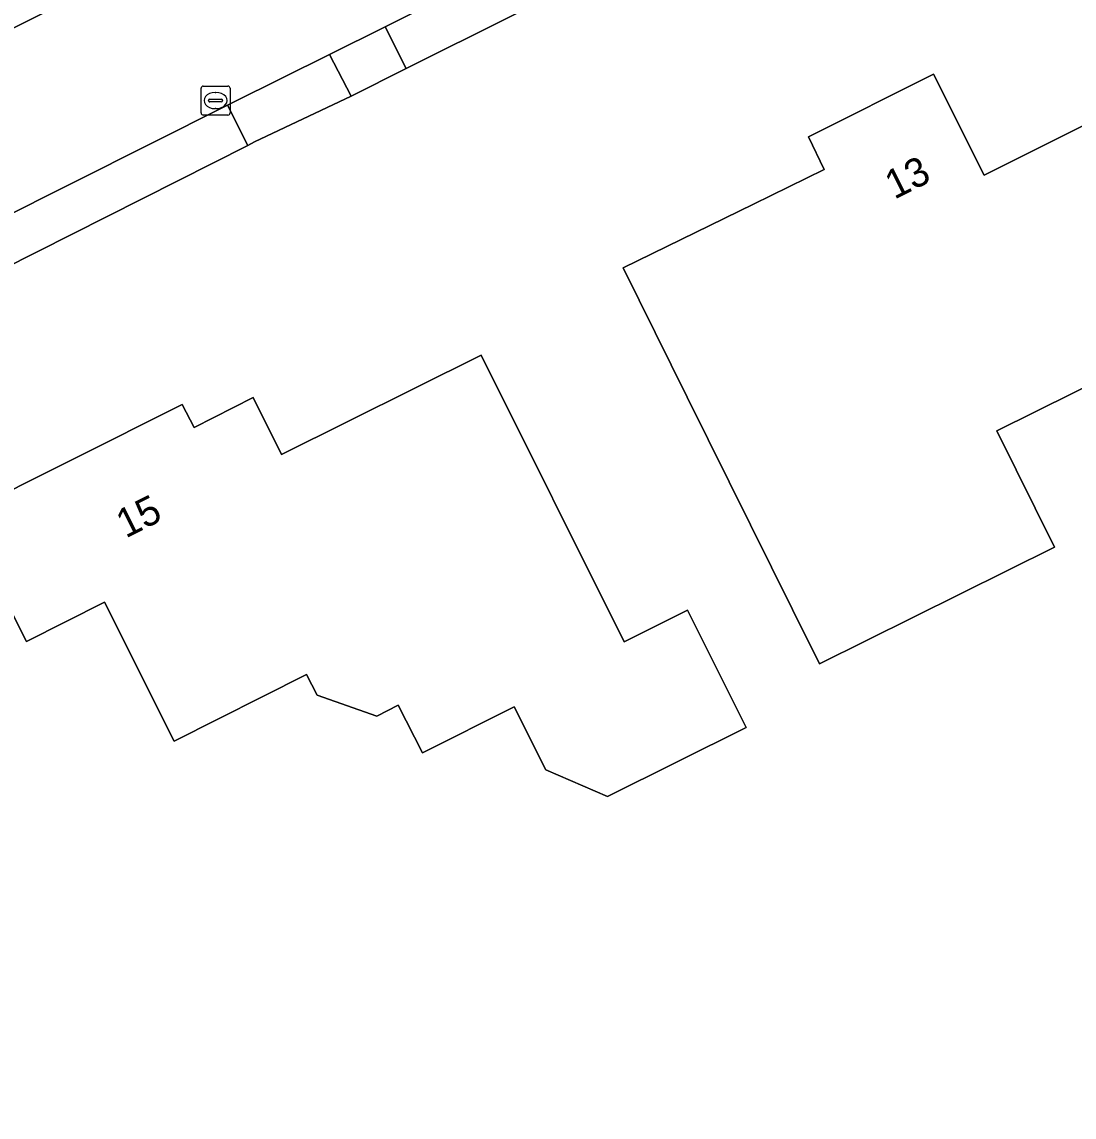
# Model space of a CAD drawing. Extents: x 157320 to 158835, y 386650 to 388491.
# Drawn here: x 158396.47 to 158432.92, y 387023.73 to 387061.67 of the extents above; entities that cross this region are included whole.
import ezdxf

# ---------------------------------------------------------------- set-up
doc = ezdxf.new("R2010")
doc.units = 0
for name, color, linetype in [('IMGEO_Berm_groen', 7, 'Continuous'), ('IMGEO_Erf', 7, 'Continuous'), ('IMGEO_Groenvoorziening', 7, 'Continuous'), ('IMGEO_Kolk', 7, 'Continuous'), ('IMGEO_Pand', 7, 'Continuous'), ('IMGEO_Pand_nummerreeks', 7, 'Continuous'), ('IMGEO_Rijbaan_lokaal_gesloten', 7, 'Continuous'), ('IMGEO_Voetpad_halfverhard', 7, 'Continuous'), ('IMGEO_Voetpad_open', 7, 'Continuous')]:
    doc.layers.add(name, color=color, linetype=linetype)

msp = doc.modelspace()

# ---------------------------------------------------------------- linework, layer by layer
at = {"layer": 'IMGEO_Berm_groen'}
msp.add_lwpolyline([(158415.179, 387070.996), (158413.936, 387073.552), (158390.827, 387061.949), (158390.738, 387061.906), (158392.005, 387059.378)], close=True, dxfattribs=at)
at = {"layer": 'IMGEO_Erf'}
msp.add_lwpolyline([(158424.326, 387067.316), (158409.775, 387060.049), (158407.876, 387059.101), (158404.527, 387057.508), (158404.288, 387057.387), (158390.893, 387050.635), (158390.572, 387050.456), (158388.447, 387049.268), (158387.528, 387048.741), (158381.13, 387045.08), (158365.561, 387037.786), (158361.263, 387035.597), (158358.348, 387034.192), (158355.614, 387032.874), (158352.957, 387031.592), (158341.848, 387026.236), (158336.855, 387023.731)], dxfattribs=at)
for points in [[(158428.051, 387059.852), (158429.801, 387056.356), (158435.97, 387059.444), (158438.213, 387054.976), (158439.627, 387052.158), (158430.244, 387047.499), (158432.241, 387043.473), (158424.099, 387039.434), (158423.165, 387041.316), (158419.519, 387048.666), (158417.297, 387053.145), (158421.817, 387055.358), (158424.264, 387056.556), (158423.712, 387057.684)], [(158417.327, 387040.195), (158419.528, 387041.292), (158421.552, 387037.23), (158416.757, 387034.84), (158414.612, 387035.762), (158413.517, 387037.946), (158410.339, 387036.353), (158409.501, 387038), (158408.757, 387037.621), (158406.694, 387038.341), (158406.331, 387039.063), (158401.738, 387036.758), (158399.326, 387041.565), (158396.622, 387040.208), (158394.413, 387044.61), (158402.024, 387048.415), (158402.429, 387047.619), (158404.48, 387048.662), (158405.462, 387046.686), (158412.377, 387050.125)]]:
    msp.add_lwpolyline(points, close=True, dxfattribs=at)
at = {"layer": 'IMGEO_Groenvoorziening'}
for points in [[(158424.326, 387067.316), (158423.604, 387068.756), (158409.052, 387061.498), (158409.775, 387060.049)], [(158404.288, 387057.387), (158403.591, 387058.779), (158390.165, 387052.056), (158389.889, 387051.918), (158390.572, 387050.456), (158390.893, 387050.635)]]:
    msp.add_lwpolyline(points, close=True, dxfattribs=at)
at = {"layer": 'IMGEO_Kolk'}
for p, q in [((158402.675, 387058.517), (158402.675, 387059.369)), ((158402.75, 387059.443), (158403.602, 387059.443)), ((158403.163, 387059.223), (158403.188, 387059.223)), ((158403.676, 387059.369), (158403.676, 387058.517)), ((158402.934, 387058.937), (158402.934, 387058.949)), ((158403.372, 387058.9), (158402.974, 387058.9)), ((158402.977, 387058.986), (158403.375, 387058.986)), ((158403.418, 387058.949), (158403.418, 387058.937)), ((158403.602, 387058.443), (158402.75, 387058.443)), ((158403.186, 387058.663), (158403.161, 387058.663))]:
    msp.add_line(p, q, dxfattribs=at)
for points in [[(158402.675, 387058.517), (158402.675, 387059.369)], [(158402.75, 387059.443), (158403.602, 387059.443)], [(158403.676, 387059.369), (158403.676, 387058.517)], [(158403.602, 387058.443), (158402.75, 387058.443)]]:
    msp.add_lwpolyline(points, dxfattribs=at)
for centre, radius, start, end in [((158402.752, 387059.367), 0.0765, 91.552, 178.448), ((158402.752, 387059.367), 0.0765, 91.552, 178.448), ((158403.6, 387059.367), 0.0765, 1.552, 88.448), ((158403.6, 387059.367), 0.0765, 1.552, 88.448), ((158402.974, 387058.946), 0.0403, 85.8775, 175.7526), ((158402.971, 387058.936), 0.0366, 178.938, 274.7102), ((158403.375, 387058.943), 0.043, 264.8664, 352.4533), ((158403.379, 387058.948), 0.0386, 1.7309, 96.639), ((158402.752, 387058.519), 0.0765, 181.552, 268.448), ((158402.752, 387058.519), 0.0765, 181.552, 268.448), ((158403.6, 387058.519), 0.0765, 271.552, 358.448), ((158403.6, 387058.519), 0.0765, 271.552, 358.448)]:
    msp.add_arc(centre, radius, start, end, dxfattribs=at)
for centre, major_axis, ratio, start_param, end_param in [((158403.162, 387058.943), (-0.387, 0.002), 0.722429, 4.712389, 7.853982), ((158403.187, 387058.943), (-0.39, 0.002), 0.717154, 1.570796, 4.712389)]:
    msp.add_ellipse(centre, major_axis=major_axis, ratio=ratio, start_param=start_param, end_param=end_param, dxfattribs=at)
at = {"layer": 'IMGEO_Pand'}
for points in [[(158423.712, 387057.684), (158424.264, 387056.556), (158421.817, 387055.358), (158417.297, 387053.145), (158419.519, 387048.666), (158423.165, 387041.316), (158424.099, 387039.434), (158432.241, 387043.473), (158430.244, 387047.499), (158439.627, 387052.158), (158438.213, 387054.976), (158435.97, 387059.444), (158429.801, 387056.356), (158428.051, 387059.852)], [(158421.552, 387037.23), (158419.528, 387041.292), (158417.327, 387040.195), (158412.377, 387050.125), (158405.462, 387046.686), (158404.48, 387048.662), (158402.429, 387047.619), (158402.024, 387048.415), (158394.413, 387044.61), (158396.622, 387040.208), (158399.326, 387041.565), (158401.738, 387036.758), (158406.331, 387039.063), (158406.694, 387038.341), (158408.757, 387037.621), (158409.501, 387038), (158410.339, 387036.353), (158413.517, 387037.946), (158414.612, 387035.762), (158416.757, 387034.84)]]:
    msp.add_lwpolyline(points, close=True, dxfattribs=at)
at = {"layer": 'IMGEO_Rijbaan_lokaal_gesloten'}
for points in [[(158415.179, 387070.996), (158392.005, 387059.378), (158390.207, 387058.483), (158383.425, 387055.083), (158372.885, 387049.837), (158359.245, 387043.002), (158353.495, 387040.129), (158349.279, 387038.02), (158346.051, 387036.405), (158338.557, 387032.656)], [(158336.2, 387025.079), (158341.18, 387027.566), (158352.213, 387033.09), (158354.869, 387034.42), (158359.307, 387036.641), (158360.393, 387037.185), (158364.741, 387039.333), (158380.131, 387047.014), (158386.719, 387050.325), (158387.648, 387050.792), (158389.889, 387051.918), (158390.165, 387052.056), (158403.591, 387058.779), (158403.798, 387058.883), (158407.127, 387060.538), (158409.052, 387061.498), (158423.604, 387068.756)]]:
    msp.add_lwpolyline(points, dxfattribs=at)
at = {"layer": 'IMGEO_Voetpad_halfverhard'}
msp.add_lwpolyline([(158409.052, 387061.498), (158407.127, 387060.538), (158407.876, 387059.101), (158409.775, 387060.049)], close=True, dxfattribs=at)
at = {"layer": 'IMGEO_Voetpad_open'}
msp.add_lwpolyline([(158407.876, 387059.101), (158407.127, 387060.538), (158403.798, 387058.883), (158403.591, 387058.779), (158404.288, 387057.387), (158404.527, 387057.508)], close=True, dxfattribs=at)

# ---------------------------------------------------------------- texts
at = {"layer": 'IMGEO_Pand_nummerreeks'}
for s, rotation, p in [('13', 26.5492, (158426.69, 387055.506)), ('15', 26.562, (158400.06, 387043.767))]:
    msp.add_text(s, height=1, rotation=rotation, dxfattribs=at).set_placement(p)

doc.saveas('drawing.dxf')
